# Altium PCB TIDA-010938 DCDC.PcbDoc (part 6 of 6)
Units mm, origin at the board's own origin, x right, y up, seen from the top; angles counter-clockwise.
Board outline 280 x 174.95 mm, 4 copper layers (Top Layer, Layer 1, Layer 2, Bottom Layer), stack 1.787 mm thick; 409 components, 218 nets, 1371 pads, 2268 vias.
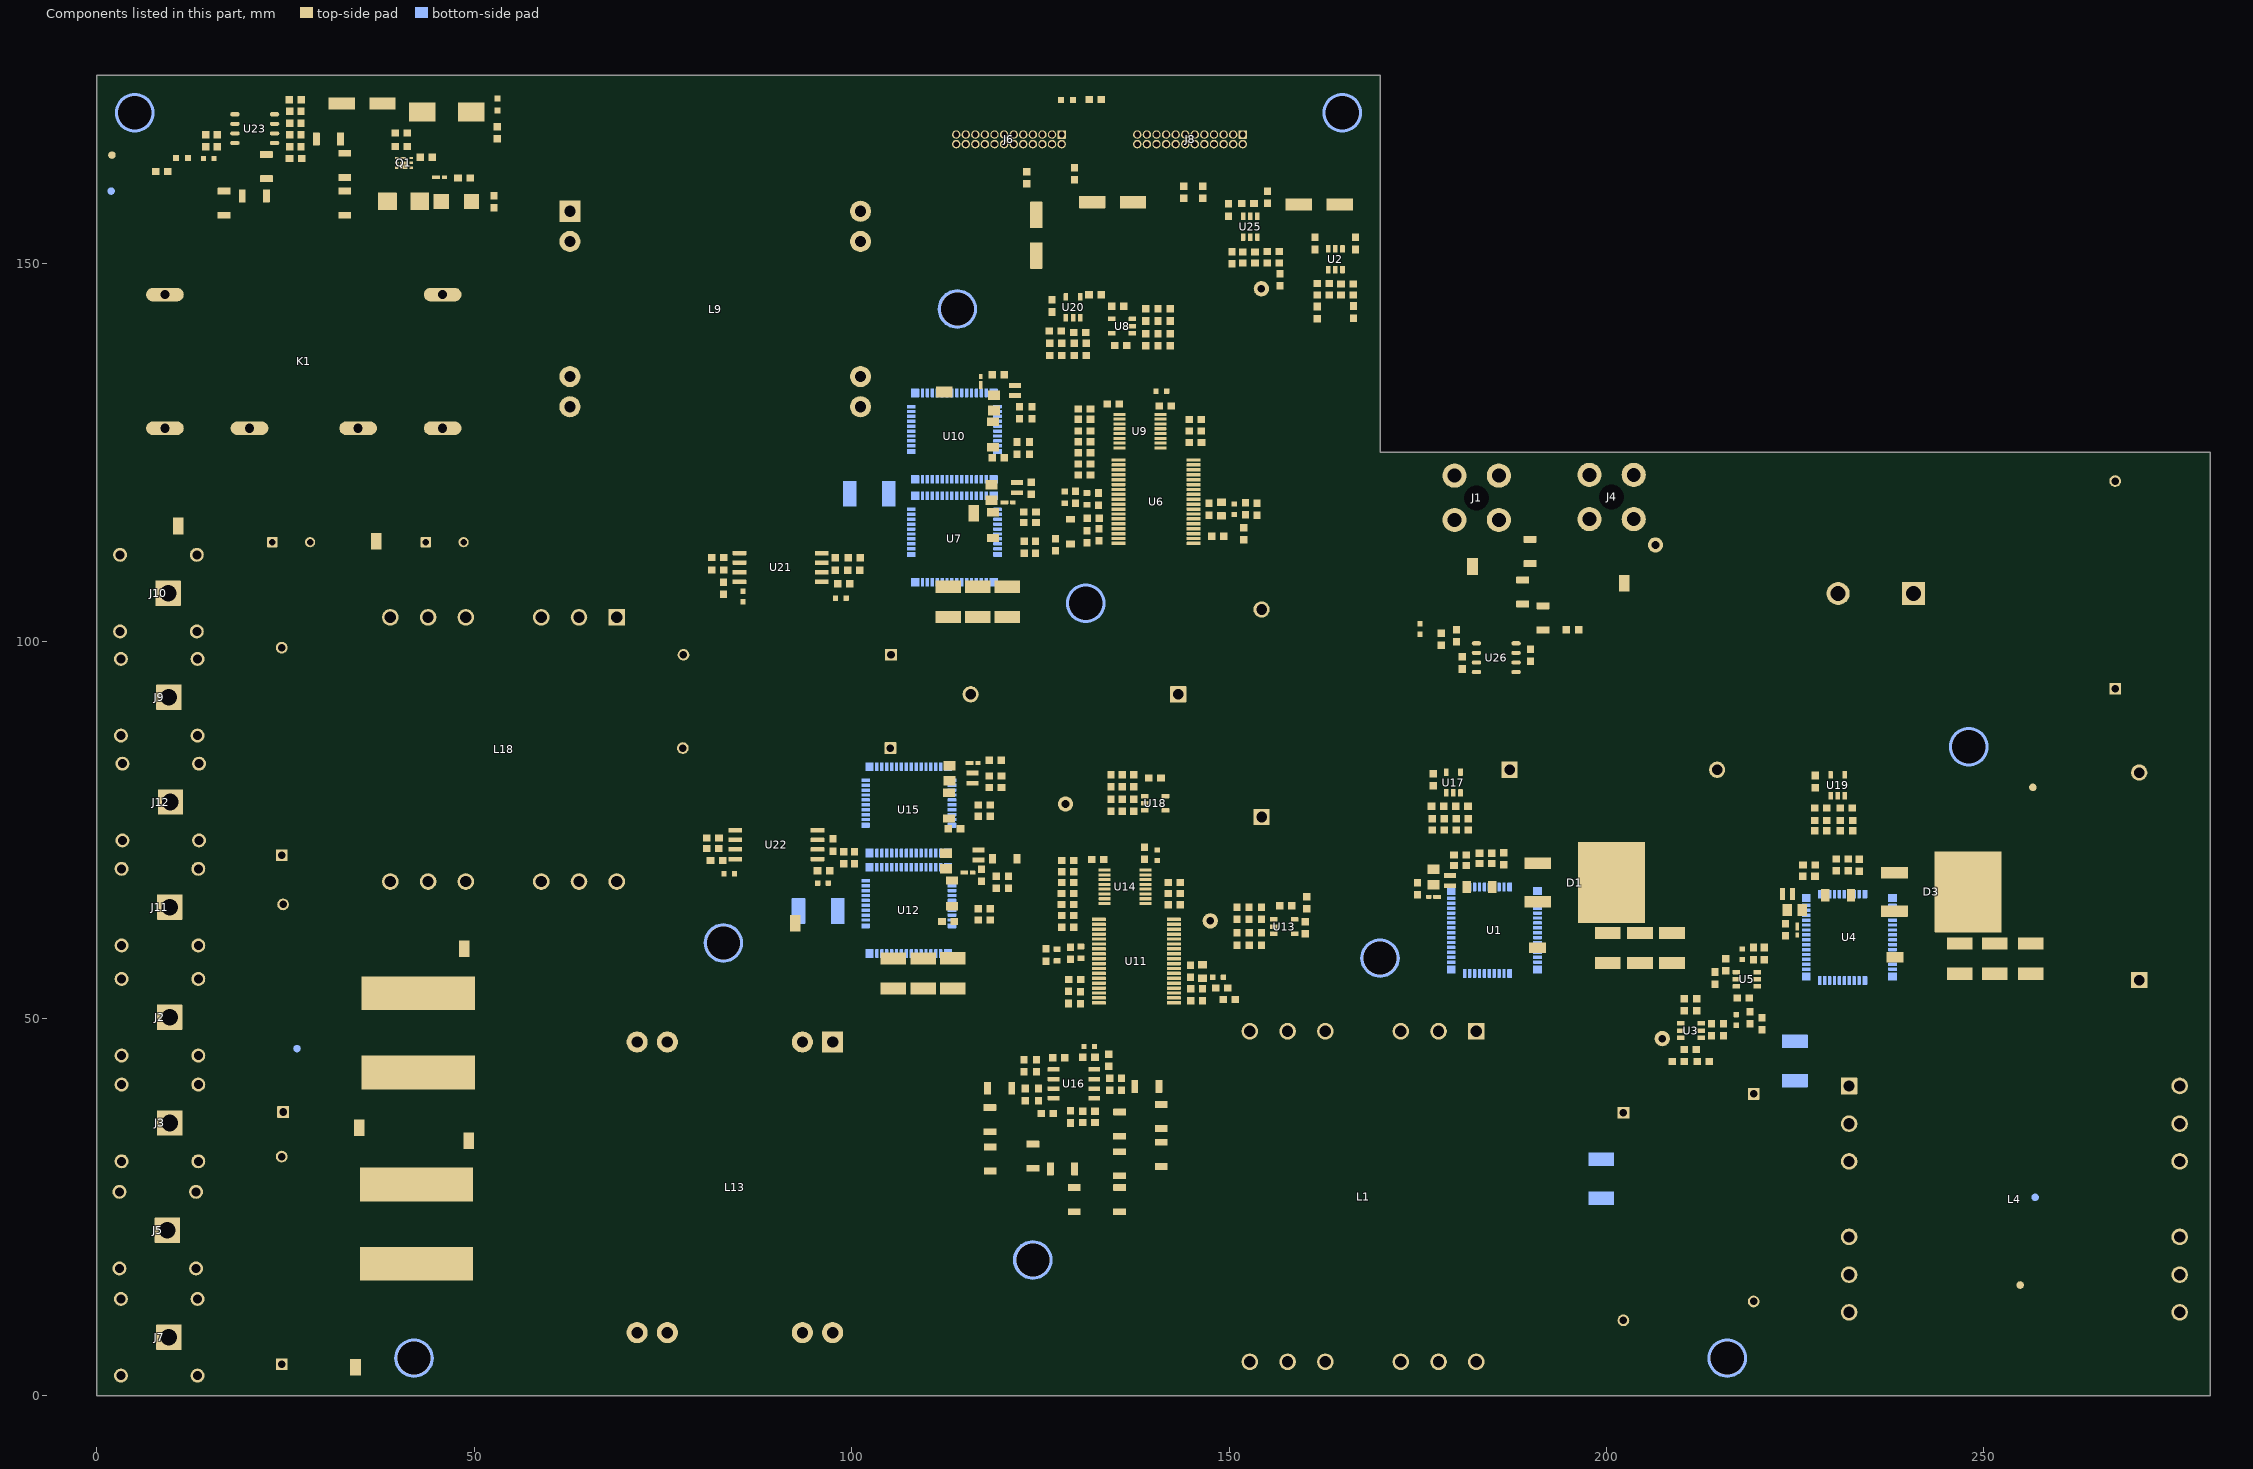
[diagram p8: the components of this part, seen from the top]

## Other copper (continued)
Layer 1:
  pour cut-out: 220.699,46.324 ccw(c221.199,46.324) 221.199,45.824 ccw(c221.199,46.324) 221.699,46.324 ccw(c221.199,46.324) 221.199,46.824 ccw(c221.199,46.324)
  pour cut-out: 219.407,46.359 ccw(c219.907,46.359) 219.907,45.859 ccw(c219.907,46.359) 220.407,46.359 ccw(c219.907,46.359) 219.907,46.859 ccw(c219.907,46.359)
  pour cut-out: 154.347,101.077 cw(c154.347,104.077) 151.347,104.077 cw(c154.347,104.077) 154.347,107.077 cw(c154.347,104.077) 157.347,104.077 cw(c154.347,104.077)
  pour cut-out: 123.998,15.05 cw(c123.998,18.05) 120.998,18.05 cw(c123.998,18.05) 123.998,21.05 cw(c123.998,18.05) 126.998,18.05 cw(c123.998,18.05)
  pour cut-out: 216,1.984 cw(c216,4.984) 213,4.984 cw(c216,4.984) 216,7.984 cw(c216,4.984) 219,4.984 cw(c216,4.984)
  pour cut-out: 248.014,83 cw(c248.014,86) 245.014,86 cw(c248.014,86) 248.014,89 cw(c248.014,86) 251.014,86 cw(c248.014,86)
  pour cut-out: 170.014,54.892 cw(c170.014,57.892) 167.014,57.892 cw(c170.014,57.892) 170.014,60.892 cw(c170.014,57.892) 173.014,57.892 cw(c170.014,57.892)
  pour cut-out: 114.014,141 cw(c114.014,144) 111.014,144 cw(c114.014,144) 114.014,147 cw(c114.014,144) 117.014,144 cw(c114.014,144)
  pour cut-out: 219.5,9.513 cw(c219.5,12.513) 216.5,12.513 cw(c219.5,12.513) 219.5,15.513 cw(c219.5,12.513) 222.5,12.513 cw(c219.5,12.513)
  pour cut-out: 202.266,7.006 cw(c202.266,10.006) 199.266,10.006 cw(c202.266,10.006) 202.266,13.006 cw(c202.266,10.006) 205.266,10.006 cw(c202.266,10.006)
  pour cut-out: 172.809,1.697 cw(c172.809,4.697) 169.809,4.697 cw(c172.809,4.697) 172.809,7.697 cw(c172.809,4.697) 175.809,4.697 cw(c172.809,4.697)
  pour cut-out: 177.809,1.697 cw(c177.809,4.697) 174.809,4.697 cw(c177.809,4.697) 177.809,7.697 cw(c177.809,4.697) 180.809,4.697 cw(c177.809,4.697)
  pour cut-out: 182.809,1.697 cw(c182.809,4.697) 179.809,4.697 cw(c182.809,4.697) 182.809,7.697 cw(c182.809,4.697) 185.809,4.697 cw(c182.809,4.697)
  pour cut-out: 162.809,1.697 cw(c162.809,4.697) 159.809,4.697 cw(c162.809,4.697) 162.809,7.697 cw(c162.809,4.697) 165.809,4.697 cw(c162.809,4.697)
  pour cut-out: 157.809,1.697 cw(c157.809,4.697) 154.809,4.697 cw(c157.809,4.697) 157.809,7.697 cw(c157.809,4.697) 160.809,4.697 cw(c157.809,4.697)
  pour cut-out: 152.809,1.598 cw(c152.809,4.598) 149.809,4.598 cw(c152.809,4.598) 152.809,7.598 cw(c152.809,4.598) 155.809,4.598 cw(c152.809,4.598)
  pour cut-out: 41.984,2.05 cw(c41.984,5.05) 38.984,5.05 cw(c41.984,5.05) 41.984,8.05 cw(c41.984,5.05) 44.984,5.05 cw(c41.984,5.05)
  pour cut-out: 77.609,82.872 cw(c77.609,85.872) 74.609,85.872 cw(c77.609,85.872) 77.609,88.872 cw(c77.609,85.872) 80.609,85.872 cw(c77.609,85.872)
  pour cut-out: 38.849,100.19 cw(c38.849,103.19) 35.849,103.19 cw(c38.849,103.19) 38.849,106.19 cw(c38.849,103.19) 41.849,103.19 cw(c38.849,103.19)
  pour cut-out: 115.742,90 cw(c115.742,93) 112.742,93 cw(c115.742,93) 115.742,96 cw(c115.742,93) 118.742,93 cw(c115.742,93)
  pour cut-out: 23.215,110.154 cw(c23.215,113.154) 20.215,113.154 cw(c23.215,113.154) 23.215,116.154 cw(c23.215,113.154) 26.215,113.154 cw(c23.215,113.154)
  pour cut-out: 77.69,95.23 cw(c77.69,98.23) 74.69,98.23 cw(c77.69,98.23) 77.69,101.23 cw(c77.69,98.23) 80.69,98.23 cw(c77.69,98.23)
  pour cut-out: 154.288,73.738 cw(c154.288,76.738) 151.288,76.738 cw(c154.288,76.738) 154.288,79.738 cw(c154.288,76.738) 157.288,76.738 cw(c154.288,76.738)
  pour cut-out: 68.849,100.19 cw(c68.849,103.19) 65.849,103.19 cw(c68.849,103.19) 68.849,106.19 cw(c68.849,103.19) 71.849,103.19 cw(c68.849,103.19)
  pour cut-out: 63.849,100.19 cw(c63.849,103.19) 60.849,103.19 cw(c63.849,103.19) 63.849,106.19 cw(c63.849,103.19) 66.849,103.19 cw(c63.849,103.19)
  pour cut-out: 58.849,100.19 cw(c58.849,103.19) 55.849,103.19 cw(c58.849,103.19) 58.849,106.19 cw(c58.849,103.19) 61.849,103.19 cw(c58.849,103.19)
  pour cut-out: 48.849,100.19 cw(c48.849,103.19) 45.849,103.19 cw(c48.849,103.19) 48.849,106.19 cw(c48.849,103.19) 51.849,103.19 cw(c48.849,103.19)
  pour cut-out: 43.849,100.19 cw(c43.849,103.19) 40.849,103.19 cw(c43.849,103.19) 43.849,106.19 cw(c43.849,103.19) 46.849,103.19 cw(c43.849,103.19)
  pour cut-out: 62.65,127.839 cw(c62.65,130.839) 59.65,130.839 cw(c62.65,130.839) 62.65,133.839 cw(c62.65,130.839) 65.65,130.839 cw(c62.65,130.839)
  pour cut-out: 62.65,131.839 cw(c62.65,134.839) 59.65,134.839 cw(c62.65,134.839) 62.65,137.839 cw(c62.65,134.839) 65.65,134.839 cw(c62.65,134.839)
  pour cut-out: 62.65,149.739 cw(c62.65,152.739) 59.65,152.739 cw(c62.65,152.739) 62.65,155.739 cw(c62.65,152.739) 65.65,152.739 cw(c62.65,152.739)
  pour cut-out: 62.65,153.739 cw(c62.65,156.739) 59.65,156.739 cw(c62.65,156.739) 62.65,159.739 cw(c62.65,156.739) 65.65,156.739 cw(c62.65,156.739)
  pour cut-out: 101.15,149.739 cw(c101.15,152.739) 98.15,152.739 cw(c101.15,152.739) 101.15,155.739 cw(c101.15,152.739) 104.15,152.739 cw(c101.15,152.739)
  pour cut-out: 101.15,153.739 cw(c101.15,156.739) 98.15,156.739 cw(c101.15,156.739) 101.15,159.739 cw(c101.15,156.739) 104.15,156.739 cw(c101.15,156.739)
  pour cut-out: 101.15,131.839 cw(c101.15,134.839) 98.15,134.839 cw(c101.15,134.839) 101.15,137.839 cw(c101.15,134.839) 104.15,134.839 cw(c101.15,134.839)
  pour cut-out: 101.15,127.839 cw(c101.15,130.839) 98.15,130.839 cw(c101.15,130.839) 101.15,133.839 cw(c101.15,130.839) 104.15,130.839 cw(c101.15,130.839)
  pour cut-out: 275.93,8.103 cw(c275.93,11.103) 272.93,11.103 cw(c275.93,11.103) 275.93,14.103 cw(c275.93,11.103) 278.93,11.103 cw(c275.93,11.103)
  pour cut-out: 275.93,13.103 cw(c275.93,16.103) 272.93,16.103 cw(c275.93,16.103) 275.93,19.103 cw(c275.93,16.103) 278.93,16.103 cw(c275.93,16.103)
  pour cut-out: 275.93,18.103 cw(c275.93,21.103) 272.93,21.103 cw(c275.93,21.103) 275.93,24.103 cw(c275.93,21.103) 278.93,21.103 cw(c275.93,21.103)
  pour cut-out: 275.93,28.103 cw(c275.93,31.103) 272.93,31.103 cw(c275.93,31.103) 275.93,34.103 cw(c275.93,31.103) 278.93,31.103 cw(c275.93,31.103)
  pour cut-out: 275.93,33.103 cw(c275.93,36.103) 272.93,36.103 cw(c275.93,36.103) 275.93,39.103 cw(c275.93,36.103) 278.93,36.103 cw(c275.93,36.103)
  pour cut-out: 275.93,38.103 cw(c275.93,41.103) 272.93,41.103 cw(c275.93,41.103) 275.93,44.103 cw(c275.93,41.103) 278.93,41.103 cw(c275.93,41.103)
  pour cut-out: 24.452,28.75 cw(c24.452,31.75) 21.452,31.75 cw(c24.452,31.75) 24.452,34.75 cw(c24.452,31.75) 27.452,31.75 cw(c24.452,31.75)
  pour cut-out: 82.984,57.05 cw(c82.984,60.05) 79.984,60.05 cw(c82.984,60.05) 82.984,63.05 cw(c82.984,60.05) 85.984,60.05 cw(c82.984,60.05)
  pour cut-out: 130.984,102.05 cw(c130.984,105.05) 127.984,105.05 cw(c130.984,105.05) 130.984,108.05 cw(c130.984,105.05) 133.984,105.05 cw(c130.984,105.05)
  pour cut-out: 164.984,167.05 cw(c164.984,170.05) 161.984,170.05 cw(c164.984,170.05) 164.984,173.05 cw(c164.984,170.05) 167.984,170.05 cw(c164.984,170.05)
  pour cut-out: 4.984,167.05 cw(c4.984,170.05) 1.984,170.05 cw(c4.984,170.05) 4.984,173.05 cw(c4.984,170.05) 7.984,170.05 cw(c4.984,170.05)
  pour cut-out: 34.909,23.5 51.409,23.5 51.409,26.5 34.909,26.5
  pour cut-out: 34,13 50.5,13 50.5,16 34,16
  pour cut-out: 263.653,124.625 270.883,124.625 270.883,117.375 263.677,117.375
  pour cut-out: 267.149,58.446 274.378,58.446 274.378,51.196 267.172,51.196
  pour cut-out: 227.149,109.625 234.378,109.625 234.378,102.375 227.172,102.375
  pour cut-out: 37.987,0.75 46.25,0.75 46.25,6.572 43.572,9.25 40.504,9.25 37.987,6.733
  pour cut-out: 122.296,13.702 125.579,13.702 128,16.122 128,19.839 125.637,22.202 122.554,22.202 119.737,19.385 119.737,16.261
  pour cut-out: 211.868,0.777 227.525,0.777 227.525,8.843 214.588,8.843 211.868,6.123
  pour cut-out: 243.754,81.75 252.017,81.75 252.017,90.25 243.754,90.25
  pour cut-out: 109.802,139.5 118.065,139.5 118.065,148 109.802,148
  pour cut-out: 41.287,115.463 45.665,115.463 45.722,115.406 45.722,111.096 41.383,111.096 41.3,111.179
  pour cut-out: 22.304,101.426 26.683,101.426 26.739,101.369 26.739,97.059 22.401,97.059 22.318,97.142
  pour cut-out: 36.025,70.508 36.025,66.008 46.825,66.008 46.825,70.508
  pour cut-out: 29.775,157.932 29.775,152.9 35.829,152.9 35.829,157.932
  pour cut-out: 68.25,11.725 68.25,5 100.75,5 100.75,11.725
  pour cut-out: 214.98,93.375 214.72,93.375 214.98,93.115
  pour cut-out: 171.894,115.242 172.513,115.248 171.903,115.25
  pour cut-out: 13.804,157.9 13.804,152.868 19.857,152.868 19.857,157.9
  pour cut-out: 103.398,87.773 107,87.773 107,84.227 103.417,84.227
  pour cut-out: 103.44,99.971 107.042,99.971 107.042,96.425 103.458,96.425
Layer 2:
  pour cut-out: 220.699,46.324 ccw(c221.199,46.324) 221.199,45.824 ccw(c221.199,46.324) 221.699,46.324 ccw(c221.199,46.324) 221.199,46.824 ccw(c221.199,46.324)
  pour cut-out: 219.407,46.359 ccw(c219.907,46.359) 219.907,45.859 ccw(c219.907,46.359) 220.407,46.359 ccw(c219.907,46.359) 219.907,46.859 ccw(c219.907,46.359)
  pour cut-out: 138.782,80.652 ccw(c139.281,80.652) 139.281,80.152 ccw(c139.281,80.652) 139.781,80.652 ccw(c139.281,80.652) 139.281,81.152 ccw(c139.281,80.652)
  pour cut-out: 179.412,96.417 ccw(c179.912,96.417) 179.912,95.917 ccw(c179.912,96.417) 180.412,96.417 ccw(c179.912,96.417) 179.912,96.917 ccw(c179.912,96.417)
  pour cut-out: 177.617,98.413 ccw(c178.117,98.413) 178.117,97.913 ccw(c178.117,98.413) 178.617,98.413 ccw(c178.117,98.413) 178.117,98.913 ccw(c178.117,98.413)
  pour cut-out: 189.416,100.205 ccw(c189.916,100.205) 189.916,99.705 ccw(c189.916,100.205) 190.416,100.205 ccw(c189.916,100.205) 189.916,100.705 ccw(c189.916,100.205)
  pour cut-out: 219.009,60.407 ccw(c219.509,60.407) 219.509,59.907 ccw(c219.509,60.407) 220.009,60.407 ccw(c219.509,60.407) 219.509,60.907 ccw(c219.509,60.407)
  pour cut-out: 124,15.05 cw(c124,18.05) 121,18.05 cw(c124,18.05) 124,21.05 cw(c124,18.05) 127,18.05 cw(c124,18.05)
  pour cut-out: 247.944,82.952 cw(c247.944,85.952) 244.944,85.952 cw(c247.944,85.952) 247.944,88.952 cw(c247.944,85.952) 250.944,85.952 cw(c247.944,85.952)
  pour cut-out: 114.025,140.878 cw(c114.025,143.878) 111.025,143.878 cw(c114.025,143.878) 114.025,146.878 cw(c114.025,143.878) 117.025,143.878 cw(c114.025,143.878)
  pour cut-out: 267.45,118.348 cw(c267.45,121.348) 264.45,121.348 cw(c267.45,121.348) 267.45,124.348 cw(c267.45,121.348) 270.45,121.348 cw(c267.45,121.348)
  pour cut-out: 170.009,54.886 cw(c170.009,57.886) 167.009,57.886 cw(c170.009,57.886) 170.009,60.886 cw(c170.009,57.886) 173.009,57.886 cw(c170.009,57.886)
  pour cut-out: 220.565,55.142 ccw(c221.065,55.142) 221.065,54.642 ccw(c221.065,55.142) 221.565,55.142 ccw(c221.065,55.142) 221.065,55.642 ccw(c221.065,55.142)
  pour cut-out: 214.921,54.599 ccw(c215.421,54.599) 215.421,54.099 ccw(c215.421,54.599) 215.921,54.599 ccw(c215.421,54.599) 215.421,55.099 ccw(c215.421,54.599)
  pour cut-out: 216.286,47.683 ccw(c216.786,47.683) 216.786,47.183 ccw(c216.786,47.683) 217.286,47.683 ccw(c216.786,47.683) 216.786,48.183 ccw(c216.786,47.683)
  pour cut-out: 209.138,50.222 ccw(c209.138,50.722) 209.638,50.722 ccw(c209.138,50.722) 209.138,51.222 ccw(c209.138,50.722) 208.638,50.722 ccw(c209.138,50.722)
  pour cut-out: 41.984,2.05 cw(c41.984,5.05) 38.984,5.05 cw(c41.984,5.05) 41.984,8.05 cw(c41.984,5.05) 44.984,5.05 cw(c41.984,5.05)
  pour cut-out: 270.574,52.131 cw(c270.574,55.131) 267.574,55.131 cw(c270.574,55.131) 270.574,58.131 cw(c270.574,55.131) 273.574,55.131 cw(c270.574,55.131)
  pour cut-out: 23.215,110.154 cw(c23.215,113.154) 20.215,113.154 cw(c23.215,113.154) 23.215,116.154 cw(c23.215,113.154) 26.215,113.154 cw(c23.215,113.154)
  pour cut-out: 215.984,2.05 cw(c215.984,5.05) 212.984,5.05 cw(c215.984,5.05) 215.984,8.05 cw(c215.984,5.05) 218.984,5.05 cw(c215.984,5.05)
  pour cut-out: 275.93,8.103 cw(c275.93,11.103) 272.93,11.103 cw(c275.93,11.103) 275.93,14.103 cw(c275.93,11.103) 278.93,11.103 cw(c275.93,11.103)
  pour cut-out: 275.93,13.103 cw(c275.93,16.103) 272.93,16.103 cw(c275.93,16.103) 275.93,19.103 cw(c275.93,16.103) 278.93,16.103 cw(c275.93,16.103)
  pour cut-out: 275.93,18.103 cw(c275.93,21.103) 272.93,21.103 cw(c275.93,21.103) 275.93,24.103 cw(c275.93,21.103) 278.93,21.103 cw(c275.93,21.103)
  pour cut-out: 275.93,28.103 cw(c275.93,31.103) 272.93,31.103 cw(c275.93,31.103) 275.93,34.103 cw(c275.93,31.103) 278.93,31.103 cw(c275.93,31.103)
  pour cut-out: 275.93,33.103 cw(c275.93,36.103) 272.93,36.103 cw(c275.93,36.103) 275.93,39.103 cw(c275.93,36.103) 278.93,36.103 cw(c275.93,36.103)
  pour cut-out: 275.93,38.103 cw(c275.93,41.103) 272.93,41.103 cw(c275.93,41.103) 275.93,44.103 cw(c275.93,41.103) 278.93,41.103 cw(c275.93,41.103)
  pour cut-out: 101.15,127.839 cw(c101.15,130.839) 98.15,130.839 cw(c101.15,130.839) 101.15,133.839 cw(c101.15,130.839) 104.15,130.839 cw(c101.15,130.839)
  pour cut-out: 101.15,131.839 cw(c101.15,134.839) 98.15,134.839 cw(c101.15,134.839) 101.15,137.839 cw(c101.15,134.839) 104.15,134.839 cw(c101.15,134.839)
  pour cut-out: 101.15,149.739 cw(c101.15,152.739) 98.15,152.739 cw(c101.15,152.739) 101.15,155.739 cw(c101.15,152.739) 104.15,152.739 cw(c101.15,152.739)
  pour cut-out: 101.15,153.739 cw(c101.15,156.739) 98.15,156.739 cw(c101.15,156.739) 101.15,159.739 cw(c101.15,156.739) 104.15,156.739 cw(c101.15,156.739)
  pour cut-out: 130.984,102.05 cw(c130.984,105.05) 127.984,105.05 cw(c130.984,105.05) 130.984,108.05 cw(c130.984,105.05) 133.984,105.05 cw(c130.984,105.05)
  pour cut-out: 164.984,167.05 cw(c164.984,170.05) 161.984,170.05 cw(c164.984,170.05) 164.984,173.05 cw(c164.984,170.05) 167.984,170.05 cw(c164.984,170.05)
  pour cut-out: 4.984,167.05 cw(c4.984,170.05) 1.984,170.05 cw(c4.984,170.05) 4.984,173.05 cw(c4.984,170.05) 7.984,170.05 cw(c4.984,170.05)
  pour cut-out: 151.94,79.3 151.94,74.3 156.811,74.3 156.811,79.3
  pour cut-out: 184.84,85.5 184.84,80.5 189.711,80.5 189.711,85.5
  pour cut-out: 140.829,95.5 140.829,90.5 145.7,90.5 145.7,95.5
  pour cut-out: 226.623,102 235.158,102 235.158,110.5 226.623,110.5
  pour cut-out: 81.962,55.75 87.419,55.75 87.419,64.25 81.519,64.25 79.156,61.887 79.156,58.556
  pour cut-out: 243.737,81.75 252.272,81.75 252.272,90.25 243.737,90.25
  pour cut-out: 41.304,115.426 45.683,115.426 45.739,115.369 45.739,111.059 41.401,111.059 41.318,111.142
  pour cut-out: 172.93,52 186.653,52 190,48.653 190,35 195.5,29.5 172.537,29.5
  pour cut-out: 142.75,87.75 130,87.75 130,85.75 142.75,85.75
  pour cut-out: 36.025,70.508 36.025,66.008 46.825,66.008 46.825,70.508
  pour cut-out: 225.73,60.279 226.492,61.04 226.492,65.737 227.244,66.489 233.453,66.489 233.792,66.15 233.792,65.422 231.04,62.67 231.04,61.702 233.691,59.051 254.298,58.995 256.221,60.919 256.221,74.193 253.532,76.883 239.803,76.883 237.299,79.388 224.342,79.388 224.342,70.991 221.734,68.383 221.734,60.279
  pour cut-out: 36.025,105.508 36.025,101.008 46.825,101.008 46.825,105.508
Bottom Layer:
  pour cut-out: 123.75,11.024 cw(c123.75,18.024) 116.75,18.024 cw(c123.75,18.024) 123.75,25.024 cw(c123.75,18.024) 130.75,18.024 cw(c123.75,18.024)
  pour cut-out: 202.266,7.006 cw(c202.266,10.006) 199.266,10.006 cw(c202.266,10.006) 202.266,13.006 cw(c202.266,10.006) 205.266,10.006 cw(c202.266,10.006)
  pour cut-out: 170,50.958 cw(c170,57.958) 163,57.958 cw(c170,57.958) 170,64.958 cw(c170,57.958) 177,57.958 cw(c170,57.958)
  pour cut-out: 82.981,53.274 cw(c82.981,60.274) 75.981,60.274 cw(c82.981,60.274) 82.981,67.274 cw(c82.981,60.274) 89.981,60.274 cw(c82.981,60.274)
  pour cut-out: 41.981,-1.976 cw(c41.981,5.024) 34.981,5.024 cw(c41.981,5.024) 41.981,12.024 cw(c41.981,5.024) 48.981,5.024 cw(c41.981,5.024)
  pour cut-out: 113.981,137.024 cw(c113.981,144.024) 106.981,144.024 cw(c113.981,144.024) 113.981,151.024 cw(c113.981,144.024) 120.981,144.024 cw(c113.981,144.024)
  pour cut-out: 247.981,79.024 cw(c247.981,86.024) 240.981,86.024 cw(c247.981,86.024) 247.981,93.024 cw(c247.981,86.024) 254.981,86.024 cw(c247.981,86.024)
  pour cut-out: 275.93,38.103 cw(c275.93,41.103) 272.93,41.103 cw(c275.93,41.103) 275.93,44.103 cw(c275.93,41.103) 278.93,41.103 cw(c275.93,41.103)
  pour cut-out: 275.93,33.103 cw(c275.93,36.103) 272.93,36.103 cw(c275.93,36.103) 275.93,39.103 cw(c275.93,36.103) 278.93,36.103 cw(c275.93,36.103)
  pour cut-out: 275.93,28.103 cw(c275.93,31.103) 272.93,31.103 cw(c275.93,31.103) 275.93,34.103 cw(c275.93,31.103) 278.93,31.103 cw(c275.93,31.103)
  pour cut-out: 275.93,18.103 cw(c275.93,21.103) 272.93,21.103 cw(c275.93,21.103) 275.93,24.103 cw(c275.93,21.103) 278.93,21.103 cw(c275.93,21.103)
  pour cut-out: 275.93,13.103 cw(c275.93,16.103) 272.93,16.103 cw(c275.93,16.103) 275.93,19.103 cw(c275.93,16.103) 278.93,16.103 cw(c275.93,16.103)
  pour cut-out: 275.93,8.103 cw(c275.93,11.103) 272.93,11.103 cw(c275.93,11.103) 275.93,14.103 cw(c275.93,11.103) 278.93,11.103 cw(c275.93,11.103)
  pour cut-out: 24.452,96.181 cw(c24.452,99.181) 21.452,99.181 cw(c24.452,99.181) 24.452,102.181 cw(c24.452,99.181) 27.452,99.181 cw(c24.452,99.181)
  pour cut-out: 130.981,98.024 cw(c130.981,105.024) 123.981,105.024 cw(c130.981,105.024) 130.981,112.024 cw(c130.981,105.024) 137.981,105.024 cw(c130.981,105.024)
  pour cut-out: 215.981,-1.976 cw(c215.981,5.024) 208.981,5.024 cw(c215.981,5.024) 215.981,12.024 cw(c215.981,5.024) 222.981,5.024 cw(c215.981,5.024)
  pour cut-out: 164.981,163.024 cw(c164.981,170.024) 157.981,170.024 cw(c164.981,170.024) 164.981,177.024 cw(c164.981,170.024) 171.981,170.024 cw(c164.981,170.024)
  pour cut-out: 4.981,163.024 cw(c4.981,170.024) -2.019,170.024 cw(c4.981,170.024) 4.981,177.024 cw(c4.981,170.024) 11.981,170.024 cw(c4.981,170.024)
  pour cut-out: 150.304,104.188 ccw(c154.304,104.188) 154.304,100.188 ccw(c154.304,104.188) 158.304,104.188 ccw(c154.304,104.188) 154.304,108.188 ccw(c154.304,104.188)
  pour cut-out: 237.124,110.125 244.353,110.125 244.353,102.875 237.147,102.875
  pour cut-out: 267.124,86.296 274.353,86.296 274.353,79.046 267.147,79.046
  pour cut-out: 263.738,97.375 270.967,97.375 270.967,90.125 263.762,90.125
  pour cut-out: 138,29.601 138,25.101 144.053,25.101 144.053,29.601
  pour cut-out: 68.286,11.711 68.286,4.986 100.786,4.986 100.786,11.711
  pour cut-out: 148.75,7.923 148.75,1 187.5,1 187.5,7.923
  pour cut-out: 56,70.5 56,66 71.171,66 71.171,70.5
  pour cut-out: 36,70.5 36,66 51.171,66 51.171,70.5
  pour cut-out: 36.822,105.508 36.822,101.008 45.975,101.008 45.975,105.508
  pour cut-out: 20.918,115.176 25.296,115.176 25.353,115.12 25.353,110.81 21.014,110.81 20.931,110.893
  pour cut-out: 95.867,112.244 95.893,112.244 95.867,112.248
  pour cut-out: 29.77,157.4 29.77,152.9 35.823,152.9 35.823,157.4
  pour cut-out: 13.825,157.45 13.825,152.95 19.878,152.95 19.878,157.45
  text ".Layer_Name" at -10.519,-151.856 h1.52

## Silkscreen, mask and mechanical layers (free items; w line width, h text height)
Top Overlay:
  text "5V" at 125.125,171.525 h0.5
  text "12V" at 51.125,161.875 h0.5
  text "3V3" at 11.025,160.425 h0.5
  text "+" at 126.282,157.057 h0.5
  text "+" at 131.391,156.756 h0.5
  text "-" at 124.335,148.177 h0.5
  text "-" at 118.345,136.606 h0.5
  text ".PRJ_Number" at 143.25,133.624 h3.05
  text "VER: .PCB_Rev" at 158.25,130.795 h3.05
  text "BAT1" at 110.75,126.746 h2
  text "DC+" at 174.5,120.25 h2
  text "DC-" at 207.25,120.25 h2
  text "-" at 178.477,117.71 h0.5 r180
  text "BAT-" at 34,116.5 h2
  text "BAT+" at 4.108,113.93 h2
  text "1" at 7.815,112.781 h0.5
  text "+" at 178.551,107.518 h0.5 r180
  text "1" at 7.688,78.497 h0.5
  text "BAT-" at 0,71.019 h2
  text "BAT2" at 103.498,70.597 h2
  text "PV1" at 183.25,60.996 h2
  text "PV2" at 230.5,59.746 h2
  text "PV1+" at 43.8,58.634 h2
  text "PV1+" at 1,56.773 h2
  text "PV1-" at 0.75,42.75 h2
  text "PV2+" at 44.319,36.308 h2
  text "PV1-" at 36.44,36.222 h2
  text "PV2+" at 1,28.45 h2
  text "PV2-" at 1.225,14.405 h2
  text "PV2-" at 32.965,8.118 h2
  text ".Layer_Name" at -10.519,-151.856 h0.5
Bottom Overlay:
  text ".Layer_Name" at -10.519,-151.856 h0.5
Top Paste:
  text ".Layer_Name" at -10.519,-151.856 h1.52
Bottom Paste:
  text ".Layer_Name" at -10.519,-151.856 h1.52
Top Solder:
  text ".Layer_Name" at -10.519,-151.856 h1.52
  text ".Layer_Name" at -10.519,-151.856 h1.52
Bottom Solder:
  text ".Layer_Name" at -10.519,-151.856 h1.52
M1 Board Outline:
  region: 183.775,135.053 183.779,135.094 183.716,135.1 183.712,135.059
  lines w0.5: 0,0 0,174.95 170,174.95 170,125 280,125 280,0 0,0
  text ".Layer_Name" at 0.125,-5.85 h1.52
M2 Board Dimensions:
  rectangle: -22,-140.21 -12.475,-137.035
  rectangle: -25.175,-137.035 -22,-133.86
  lines w0.178: -25.175,-137.035 0.225,-137.035 ; -22,-140.21 -22,-133.86 ; -18.825,-140.21 -18.825,-133.86 ; -12.475,-140.21 -12.475,-133.86 ; -6.125,-140.21 -6.125,-133.86 ; -25.175,-140.21 -25.175,-133.86 0.225,-133.86 0.225,-140.21 -25.175,-140.21
  text ".Layer_Name" at -7.675,-151.856 h1.52
M3 3D STEP Top:
  text ".Layer_Name" at -10.519,-151.856 h1.52
M4 3D STEP Bottom:
  text ".Layer_Name" at -10.519,-151.856 h1.52
M5 Assembly Top:
  lines w0.254: -32.592,-153.676 135.048,-153.676 ; -32.592,-148.512 135.099,-148.512 ; -32.592,-143.347 -32.592,-158.841 69.135,-158.841 135.099,-158.841 135.099,-143.347 -32.579,-143.347 -32.579,-158.841 7.439,-158.841 ; 30.019,-158.841 30.019,-143.347 ; 62.201,-148.512 62.201,-143.347 ; 83.537,-148.512 83.537,-143.347 ; 99.336,-159.006 99.336,-153.854
  text "COMPONENTS MARKED 'DNP' SHOULD NOT BE POPULATED." at 4.124,-138.14 h1.52
  text "ASSEMBLY VARIANT:" at 4.111,-141.074 h1.52
  text ".VariantName" at 30.426,-141.074 h1.52
  text "PCB VIEWED FROM TOP SIDE" at -30.979,-146.704 h1.52
  text "BOARD #:" at 31.924,-146.704 h1.52
  text ".PRJ_Number" at 45.78,-146.704 h1.52
  text "REV:" at 67.23,-146.704 h1.52
  text ".PCB_Rev" at 74.634,-146.704 h1.52
  text "SVN REV:" at 88.515,-146.704 h1.52
  text ".VersionControl_RevNumber" at 101.368,-146.704 h1.52
  text "PLOT NAME =" at -30.979,-157.084 h1.52
  text ".plot_File_Name" at -10.519,-157.084 h1.52
  text "GENERATED    :" at 31.975,-157.084 h1.52
  text ".Print_Date" at 54.06,-157.084 h1.52
  text ".Print_Time" at 72.577,-157.084 h1.52
  text "TEXAS INSTRUMENTS" at 104.695,-157.084 h1.52
M6 Assembly Bottom:
  lines w0.254: -32.604,-148.524 135.086,-148.524 ; -32.554,-153.689 135.086,-153.689 ; 3.159,-159.019 3.159,-153.867 ; 18.958,-148.524 18.958,-143.36 ; 40.294,-148.524 40.294,-143.36 ; 72.475,-158.854 72.475,-143.36 ; 95.056,-158.854 135.074,-158.854 135.074,-143.36 -32.604,-143.36 -32.604,-158.854 33.359,-158.854 135.086,-158.854 135.086,-143.36
  text "COMPONENTS MARKED 'DNP' SHOULD NOT BE POPULATED." at 129.816,-138.127 h1.52
  text ".VariantName" at 103.298,-141.074 h1.52
  text "ASSEMBLY VARIANT:" at 129.689,-141.074 h1.52
  text ".VersionControl_RevNumber" at 1.127,-146.717 h1.52
  text "SVN REV:" at 13.979,-146.717 h1.52
  text ".PCB_Rev" at 27.86,-146.717 h1.52
  text "REV:" at 35.264,-146.717 h1.52
  text ".PRJ_Number" at 56.715,-146.717 h1.52
  text "BOARD #:" at 70.57,-146.717 h1.52
  text "PCB VIEWED FROM BOTTOM SIDE" at 133.473,-146.717 h1.52
  text "TEXAS INSTRUMENTS" at -2.201,-157.097 h1.52
  text ".Print_Time" at 29.918,-157.097 h1.52
  text ".Print_Date" at 48.434,-157.097 h1.52
  text "GENERATED    :" at 70.52,-157.097 h1.52
  text ".plot_File_Name" at 113.014,-157.097 h1.52
  text "PLOT NAME =" at 133.473,-157.097 h1.52
M7 LPKF Text Top:
  text "Venkatesh" at 236.896,95.738 h1.52
M9 Title Sheet:
  drawing of 56 lines, arcs and shapes, not listed
  text "1" at 1.707,209.837 h1.78
  text "2" at 86.179,209.837 h1.78
  text "3" at 170.761,209.837 h1.78
  text "4" at 255.47,209.837 h1.78
  text "5" at 339.925,209.837 h1.78
  text "6" at 424.634,209.837 h1.78
  text "A" at -36.935,164.676 h1.78
  text "A" at 463.445,164.676 h1.78
  text "B" at -36.935,69.426 h1.78
  text "B" at 463.445,69.426 h1.78
  text "C" at -36.935,-25.824 h1.78
  text "C" at 463.445,-25.824 h1.78
  text "D" at -36.935,-121.074 h1.78
  text "D" at 463.445,-121.074 h1.78
  text "PROJECT TITLE:" at 384.857,-123.233 h1.14
  text ".PRJ_Title" at 386.127,-126.619 h1.78
  text "DESIGNED FOR:" at 384.857,-130.878 h1.14
  text ".PRJ_Customer" at 386.127,-134.434 h1.78
  text "FILE NAME:" at 384.857,-138.498 h1.14
  text ".PCB_File_Name_No_Path" at 386.127,-141.546 h1.78
  text "Texas Instruments (TI) and/or its licensors do not warrant the accuracy or completeness of this specification" at 258.632,-145.657 h1.14
  text "ENGINEER:" at 384.857,-145.864 h1.14
  text "LAYOUT BY:" at 423.084,-145.864 h1.14
  text "or any information contained therein. TI and/or its licensors do not warrant that this design will meet" at 257.489,-148.519 h1.14
  text ".PRJ_Engineer" at 386.127,-149.801 h1.78
  text ".PCB_Layout" at 424.367,-149.801 h1.78
  text "the specifications, will be suitable for your application or fit for any particular purpose, or will operate in" at 257.489,-151.38 h1.14
  text ".Layer_Name" at -10.519,-151.856 h1.52
  text "ALTIUM DESIGNER VERSION:" at 423.084,-153.738 h1.14
  text "an implementation. TI and/or its licensors do not warrant that the design is production worthy. You should" at 257.489,-154.242 h1.14
  text "completely validate and test your design implementation to confirm the system functionality for your application." at 258.632,-157.104 h1.14
  text ".print_Scale" at 386.127,-157.125 h1.78
  text ".Application_BuildNumber" at 424.367,-157.125 h1.78
  text "1" at 1.707,-163.543 h1.78
  text "2" at 86.179,-163.543 h1.78
  text "3" at 170.761,-163.543 h1.78
  text "4" at 255.47,-163.543 h1.78
  text "5" at 339.925,-163.543 h1.78
  text "6" at 424.634,-163.543 h1.78
M10 Fab Notes:
  drawing of 189 lines, arcs and shapes, not listed
  text "DESIGN INFORMATION" at 411.147,31.625 h1.52
  text "MIN. TRACK WIDTH:" at 394.775,28.269 h1.52
  text "8" at 422.619,28.27 h1.52
  text "MIL" at 426.55,28.269 h1.52
  text "MIN. CLEARANCE:" at 394.775,25.117 h1.52
  text "MIL" at 426.55,25.117 h1.52
  text "7.874" at 418.3,25 h1.52
  text "MIN. VIA PAD SIZE:" at 394.775,21.964 h1.52
  text "24" at 421.858,21.964 h1.52
  text "MIL" at 426.55,21.964 h1.52
  text "0.05mm (2MIL)" at 412.428,18.664 h1.52
  text "MINIMUM ANNULAR RING" at 386.412,18.456 h1.52
  text "EXTERNAL" at 430.411,18.456 h1.52
  text "PER" at 391.492,15.658 h1.52
  text "IPC-D-275 CLASS 2 LEVEL C" at 397.08,15.658 h1.52
  text "MIL, HOLES" at 434.881,13.106 h1.52
  text "+/-" at 424.913,12.888 h1.52
  text "+/-" at 446.605,12.888 h1.52
  text "REGISTRATION TOLERANCES:" at 386.412,12.861 h1.52
  text "METAL" at 416.887,12.861 h1.52
  text "5" at 431.522,12.861 h1.52
  text "3" at 452.68,12.861 h1.52
  text "MIL" at 455.633,12.861 h1.52
  text "HOLE SIZE TOLERANCE (UNLESS OTHERWISE SPECIFIED):" at 386.412,10.364 h1.52
  text "+/-" at 446.605,10.291 h1.52
  text "3" at 452.68,10.264 h1.52
  text "MIL" at 455.633,10.264 h1.52
  text "MATERIAL:" at 384.513,6.768 h1.52
  text "FR-4 High Tg" at 409.569,3.503 h1.52
  text "X" at 405.9,3.3 h1.52
  text "FR-4" at 395.207,3.185 h1.52
  text "OTHER" at 433.002,3.185 h1.52
  text "62 MIL (1.6mm) +/-10%" at 403.337,-0.448 h1.52
  text "X" at 400.287,-0.51 h1.52
  text "THICKNESS:" at 386.412,-0.656 h1.52
  text "OTHER" at 435.974,-0.656 h1.52
  text "TOLERANCE:" at 386.412,-4.17 h1.52
  text "X" at 407.958,-4.17 h1.52
  text "ANSI IPC-6012 TYPE 3 CLASS 2" at 412.479,-4.17 h1.52
  text "OTHER +/-" at 412.479,-7.832 h1.52
  text "BOW & TWIST:" at 386.412,-11.52 h1.52
  text "X" at 407.958,-11.52 h1.52
  text "ANSI IPC-6012 TYPE 3 CLASS 2" at 412.479,-11.52 h1.52
  text "OTHER +/-" at 412.479,-15.246 h1.52
  text "DRILLING:" at 384.513,-18.564 h1.52
  text "NC_DRILL FILES" at 429.243,-21.235 h1.52
  text "REFERENCE:" at 386.412,-21.335 h1.52
  text "X" at 403.106,-21.338 h1.52
  text "AS SHOWN" at 407.627,-21.335 h1.52
  text "X" at 425.992,-21.335 h1.52
  text "OTHER" at 436.812,-24.949 h1.52
  text "PTH COPPER THICKNESS:" at 386.404,-25.038 h1.52
  text "X" at 415.341,-25.038 h1.52
  text "20-30 um" at 418.592,-25.038 h1.52
  text "BOARD FINISH:" at 384.513,-28.787 h1.52
  text "SILKSCREEN:" at 388.456,-31.584 h1.52
  text "X" at 412.784,-31.584 h1.52
  text "TOP" at 415.755,-31.584 h1.52
  text "X" at 425.738,-31.584 h1.52
  text "BOTTOM" at 428.735,-31.584 h1.52
  text "SILKSCREEN COLOR:" at 388.456,-35.526 h1.52
  text "X" at 412.758,-35.526 h1.52
  text "WHITE" at 415.755,-35.526 h1.52
  text "OTHER" at 428.735,-35.526 h1.52
  text "X" at 416.086,-39.17 h1.52
  text "GREEN" at 419.083,-39.17 h1.52
  text "OTHER" at 434.78,-39.17 h1.52
  text "SOLDER RESIST COLOR:" at 388.456,-39.344 h1.52
  text "X" at 416.086,-43.088 h1.52
  text "MATTE" at 419.083,-43.088 h1.52
  text "SEMI-GLOSS" at 434.768,-43.104 h1.52
  text "IMMERSION GOLD (ENIG)" at 411.463,-47.476 h1.52
  text "ENEPIG" at 445.436,-47.66 h1.52
  text "SURFACE FINISH:" at 384.513,-47.685 h1.52
  text "X" at 406.942,-47.685 h1.52
  text "IMM. TIN/SILVER OR EQUIV" at 392.884,-51.173 h1.52
  text "OTHER" at 429.243,-51.273 h1.52
  text "ARRAY/PANEL:" at 384.513,-55.219 h1.52
  text "CUT AND TRIM PER M1 BOARD OUTLINE" at 411.463,-55.428 h1.52
  text "N.C. ROUTE" at 411.463,-58.882 h1.52
  text "X" at 428.938,-58.882 h1.52
  text "V. SCORE" at 433.459,-58.882 h1.52
  text "CERTIFICATION:" at 384.513,-62.162 h1.52
  text "MATERIALS AND WORKMANSHIP FOR ALL PCBS" at 402.928,-62.162 h1.52
  text "TO MEET OR EXCEED THE REQUIREMENTS OF:" at 402.928,-64.551 h1.52
  text "X" at 393.721,-67.818 h1.52
  text "ANSI IPC-A-600F CLASS ->" at 396.972,-67.818 h1.52
  text "X" at 438.831,-67.818 h1.52
  text "2" at 441.625,-67.818 h1.52
  text "1" at 433.624,-67.856 h1.52
  text "3" at 450.617,-67.856 h1.52
  text "X" at 414.346,-71.569 h1.52
  text "RoHS" at 417.597,-71.569 h1.52
  text "OTHER" at 433.965,-71.569 h1.52
  text "PER ORDER" at 444.05,-71.569 h1.52
  text "ALL BOARDS MUST MEET OR EXCEED UL94-V0 REQUIREMENTS." at 385.213,-75.476 h1.52
  text "PCB MUST BEAR THE UL94V-0 UL REGISTERED MATERIAL ID NUMBER" at 385.213,-78.424 h1.52
  text "ADDITIONAL REQUIREMENTS:" at 384.513,-82.728 h1.52
  text "MICROSECTION:" at 386.412,-85.449 h1.52
  text "YES" at 409.418,-85.449 h1.52
  text "REQUIRED" at 431.3,-89.115 h1.52
  text "BARE BOARD ELEC. TEST:" at 386.412,-89.187 h1.52
  text "NONE" at 419.578,-89.187 h1.52
  text "X" at 428.303,-89.187 h1.52
  text "PER ORDER" at 446.337,-89.187 h1.52
  text "XX MIL VIAS REQUIRE NON-CONDUCTIVE FILL AND PLANARIZE" at 390.683,-94.393 h1.5
  text "XX MIL VIAS REQUIRE CONDUCTIVE FILL AND PLANARIZE" at 390.887,-97.034 h1.52
  text "OUTER XX MIL TRACES REQUIRE 50 OHM SINGLE-ENDED IMPEDANCE" at 390.862,-101.184 h1.47
  text "LAYER 2 & 3 (INNER LAYERS) XX MIL WIDE, XX MIL SPACE / TRACES REQUIRE 100 OHM DIFFERENTIAL IMPEDANCE" at 390.658,-107.171 h1.52
  text ".Layer_Name" at -10.519,-151.856 h1.52
M11 Gerber Information:
  lines w0.254: -32.592,-153.676 135.048,-153.676 ; -32.592,-148.512 135.099,-148.512 ; -32.592,-143.347 -32.592,-158.841 69.135,-158.841 135.099,-158.841 135.099,-143.347 -32.579,-143.347 -32.579,-158.841 7.439,-158.841 ; 30.019,-158.841 30.019,-143.347 ; 62.201,-148.512 62.201,-143.347 ; 83.537,-148.512 83.537,-143.347 ; 99.336,-159.006 99.336,-153.854
  text "ALL ARTWORK VIEWED FROM TOP SIDE" at -30.979,-146.704 h1.52
  text "BOARD #:" at 31.924,-146.704 h1.52
  text ".PRJ_Number" at 45.78,-146.704 h1.52
  text "REV:" at 67.23,-146.704 h1.52
  text ".PCB_Rev" at 74.634,-146.704 h1.52
  text "SVN REV:" at 88.515,-146.704 h1.52
  text ".VersionControl_RevNumber" at 101.368,-146.704 h1.52
  text "LAYER NAME =" at -30.979,-151.856 h1.52
  text "PLOT NAME =" at -30.979,-157.084 h1.52
  text ".plot_File_Name" at -10.519,-157.084 h1.52
  text "GENERATED    :" at 31.975,-157.084 h1.52
  text ".Print_Date" at 54.06,-157.084 h1.52
  text ".Print_Time" at 72.577,-157.084 h1.52
  text "TEXAS INSTRUMENTS" at 104.695,-157.084 h1.52
M12 Stackup:
  text ".Layer_Name" at -10.519,-151.856 h1.52
M13 Component Bodies Top:
  text ".Layer_Name" at -10.519,-151.856 h1.52
M14 Component Bodies Bottom:
  text ".Layer_Name" at -10.519,-151.856 h1.52
M15 Courtyards Top:
  text ".Layer_Name" at -10.519,-151.856 h1.52
M16 Courtyards Bottom:
  text ".Layer_Name" at -10.519,-151.856 h1.52
Drill Drawing:
  text ".Layer_Name" at -10.519,-151.856 h1.52
M17 Embedded Cavity:
  text ".Layer_Name" at -10.519,-151.856 h1.52
M18 Embedded Assembly:
  text ".Layer_Name" at -10.519,-151.856 h1.52
M19 Embedded Keepout:
  text ".Layer_Name" at -9.175,-151.55 h1.52
Mechanical 20:
  lines w0.001: 0,0 280,0 ; 0,0 0,174.95 ; 0,0 280,0 ; 0,0 0,174.95 ; 0,0 280,0 ; 0,0 0,174.95 ; 0,174.95 170,174.95 ; 0,174.95 170,174.95 ; 0,174.95 170,174.95 ; 170,125 170,174.95 ; 170,125 280,125 ; 170,125 170,174.95 ; 170,125 280,125 ; 170,125 170,174.95 ; 170,125 280,125 ; 280,0 280,125 ; 280,0 280,125 ; 280,0 280,125

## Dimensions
-25.175,-140.21 to 0.225,-140.21 on M2 Board Dimensions
-0.175,9.95 to 280,125 on M2 Board Dimensions
0,0 to 170,174.95 on M2 Board Dimensions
